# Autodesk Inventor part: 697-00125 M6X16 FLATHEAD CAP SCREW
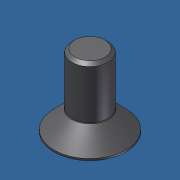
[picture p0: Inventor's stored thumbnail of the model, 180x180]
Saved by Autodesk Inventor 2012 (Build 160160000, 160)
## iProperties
Created: 2013-10
Part Number: 697-00125 M6X16 FLATHEAD CAP SCREW
Material: Default
Document SubType Name: Modeling
Designer: Admin
Density: 1 g/cm^3
Author: Admin
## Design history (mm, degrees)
node "697-00125 M6X16 FLATHEAD CAP SCREW1"
node "Base1"
body "Solid1"
